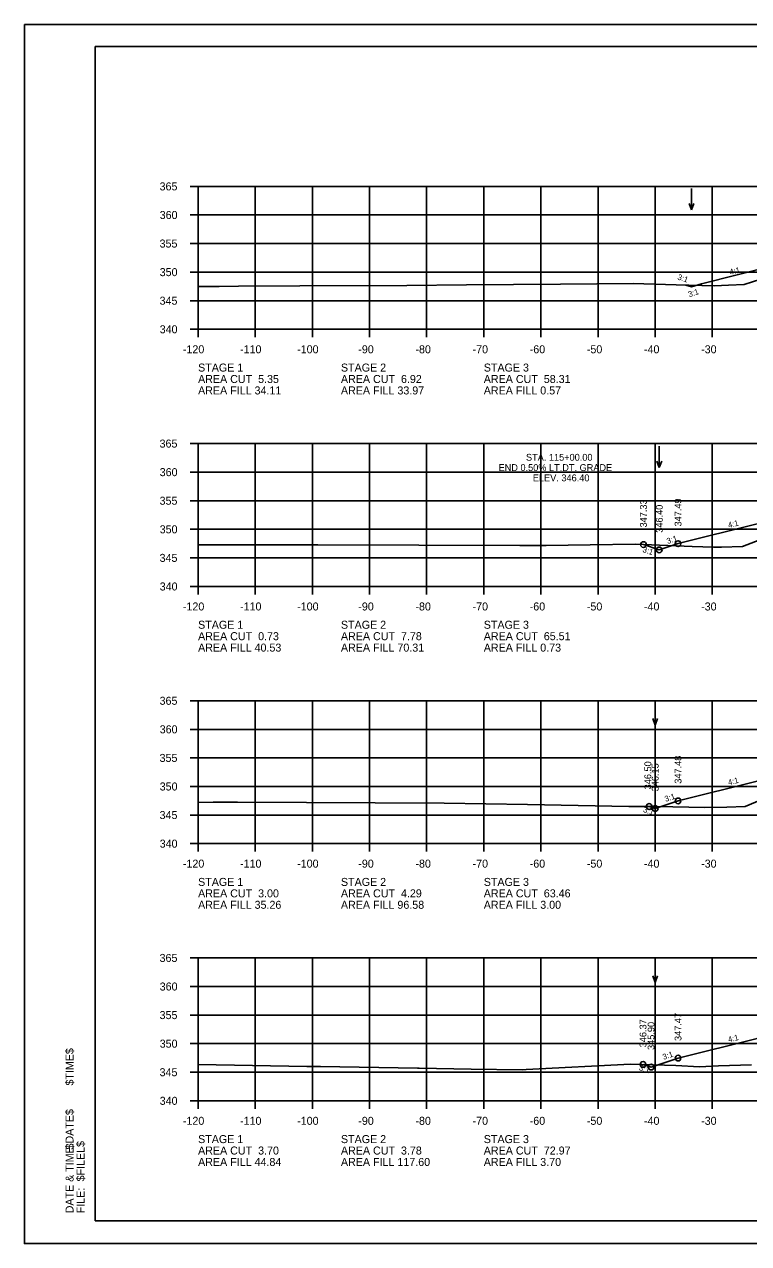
# Model space of a CAD drawing. Extents: x 1630712 to 1632516, y 782146 to 785403.
# Drawn here: x 1632182.6 to 1632309.3, y 784976.7 to 785190 of the extents above; entities that cross this region are included whole.
import ezdxf

# ---------------------------------------------------------------- set-up
doc = ezdxf.new("R2010")
doc.units = 0
for name, color, linetype in [('Default', 7, 'Continuous'), ('Notes', 7, 'Continuous'), ('R_Axis', 7, 'Continuous'), ('R_Axis Annot', 7, 'Continuous'), ('R_Border', 7, 'Continuous'), ('R_Exist Surface', 7, 'Continuous'), ('R_Fin Surface', 7, 'Continuous'), ('R_Grid', 7, 'Continuous'), ('R_No Plot', 7, 'Continuous'), ('R_Water Annot', 7, 'Continuous'), ('R_Xsect Elev', 7, 'Continuous'), ('R_Xsect Slope', 7, 'Continuous')]:
    doc.layers.add(name, color=color, linetype=linetype)

msp = doc.modelspace()

# ---------------------------------------------------------------- linework, layer by layer
at = {"layer": 'R_Axis'}
for p, q in [((1632211.56, 785161.65), (1632212.96, 785161.65)), ((1632212.96, 785136.65), (1632212.96, 785161.65)), ((1632211.56, 785156.65), (1632212.96, 785156.65)), ((1632211.56, 785151.65), (1632212.96, 785151.65)), ((1632211.56, 785146.65), (1632212.96, 785146.65)), ((1632211.56, 785141.65), (1632212.96, 785141.65)), ((1632211.56, 785136.65), (1632212.96, 785136.65)), ((1632212.96, 785136.65), (1632492.96, 785136.65)), ((1632212.96, 785135.25), (1632212.96, 785136.65)), ((1632222.96, 785135.25), (1632222.96, 785136.65)), ((1632232.96, 785135.25), (1632232.96, 785136.65)), ((1632242.96, 785135.25), (1632242.96, 785136.65)), ((1632252.96, 785135.25), (1632252.96, 785136.65)), ((1632262.96, 785135.25), (1632262.96, 785136.65)), ((1632272.96, 785135.25), (1632272.96, 785136.65)), ((1632282.96, 785135.25), (1632282.96, 785136.65)), ((1632292.96, 785135.25), (1632292.96, 785136.65)), ((1632302.96, 785135.25), (1632302.96, 785136.65)), ((1632211.56, 785116.65), (1632212.96, 785116.65)), ((1632212.96, 785091.65), (1632212.96, 785116.65)), ((1632211.56, 785111.65), (1632212.96, 785111.65)), ((1632211.56, 785106.65), (1632212.96, 785106.65)), ((1632211.56, 785101.65), (1632212.96, 785101.65)), ((1632211.56, 785096.65), (1632212.96, 785096.65)), ((1632211.56, 785091.65), (1632212.96, 785091.65)), ((1632212.96, 785091.65), (1632492.96, 785091.65)), ((1632212.96, 785090.25), (1632212.96, 785091.65)), ((1632222.96, 785090.25), (1632222.96, 785091.65)), ((1632232.96, 785090.25), (1632232.96, 785091.65)), ((1632242.96, 785090.25), (1632242.96, 785091.65)), ((1632252.96, 785090.25), (1632252.96, 785091.65)), ((1632262.96, 785090.25), (1632262.96, 785091.65)), ((1632272.96, 785090.25), (1632272.96, 785091.65)), ((1632282.96, 785090.25), (1632282.96, 785091.65)), ((1632292.96, 785090.25), (1632292.96, 785091.65)), ((1632302.96, 785090.25), (1632302.96, 785091.65)), ((1632211.56, 785071.65), (1632212.96, 785071.65)), ((1632212.96, 785046.65), (1632212.96, 785071.65)), ((1632211.56, 785066.65), (1632212.96, 785066.65)), ((1632211.56, 785061.65), (1632212.96, 785061.65)), ((1632211.56, 785056.65), (1632212.96, 785056.65)), ((1632211.56, 785051.65), (1632212.96, 785051.65)), ((1632211.56, 785046.65), (1632212.96, 785046.65)), ((1632212.96, 785046.65), (1632492.96, 785046.65)), ((1632212.96, 785045.25), (1632212.96, 785046.65)), ((1632222.96, 785045.25), (1632222.96, 785046.65)), ((1632232.96, 785045.25), (1632232.96, 785046.65)), ((1632242.96, 785045.25), (1632242.96, 785046.65)), ((1632252.96, 785045.25), (1632252.96, 785046.65)), ((1632262.96, 785045.25), (1632262.96, 785046.65)), ((1632272.96, 785045.25), (1632272.96, 785046.65)), ((1632282.96, 785045.25), (1632282.96, 785046.65)), ((1632292.96, 785045.25), (1632292.96, 785046.65)), ((1632302.96, 785045.25), (1632302.96, 785046.65)), ((1632211.56, 785026.65), (1632212.96, 785026.65)), ((1632212.96, 785001.65), (1632212.96, 785026.65)), ((1632211.56, 785021.65), (1632212.96, 785021.65)), ((1632211.56, 785016.65), (1632212.96, 785016.65)), ((1632211.56, 785011.65), (1632212.96, 785011.65)), ((1632211.56, 785006.65), (1632212.96, 785006.65)), ((1632211.56, 785001.65), (1632212.96, 785001.65)), ((1632212.96, 785001.65), (1632492.96, 785001.65)), ((1632212.96, 785000.25), (1632212.96, 785001.65)), ((1632222.96, 785000.25), (1632222.96, 785001.65)), ((1632232.96, 785000.25), (1632232.96, 785001.65)), ((1632242.96, 785000.25), (1632242.96, 785001.65)), ((1632252.96, 785000.25), (1632252.96, 785001.65)), ((1632262.96, 785000.25), (1632262.96, 785001.65)), ((1632272.96, 785000.25), (1632272.96, 785001.65)), ((1632282.96, 785000.25), (1632282.96, 785001.65)), ((1632292.96, 785000.25), (1632292.96, 785001.65)), ((1632302.96, 785000.25), (1632302.96, 785001.65))]:
    msp.add_line(p, q, dxfattribs=at)
at = {"layer": 'R_Border'}
for p, q in [((1632194.96, 785186.11), (1632511.14, 785186.11)), ((1632194.96, 784980.65), (1632194.96, 785186.11)), ((1632511.14, 784980.65), (1632194.96, 784980.65))]:
    msp.add_line(p, q, dxfattribs=at)
at = {"layer": 'R_Exist Surface'}
for points in [[(1632212.96, 785144.13), (1632216.65, 785144.16), (1632220.05, 785144.17), (1632230.79, 785144.24), (1632249.48, 785144.34), (1632259.91, 785144.4), (1632276.37, 785144.53), (1632289.09, 785144.64), (1632296.61, 785144.43), (1632303.35, 785144.26), (1632305.79, 785144.36), (1632308.53, 785144.47), (1632314.35, 785146.35)], [(1632212.96, 785098.92), (1632214.26, 785098.92), (1632223.77, 785098.93), (1632233.9, 785098.95), (1632269.28, 785098.79), (1632273.9, 785098.81), (1632281.6, 785098.95), (1632289.44, 785099.03), (1632299.42, 785098.66), (1632303.17, 785098.51), (1632304.56, 785098.55), (1632308.22, 785098.67), (1632312.8, 785100.37)], [(1632212.96, 785053.87), (1632215.59, 785053.88), (1632219.88, 785053.88), (1632256.02, 785053.73), (1632270.59, 785053.48), (1632288.33, 785053.17), (1632293.26, 785053.14), (1632301.67, 785052.95), (1632305.52, 785053.05), (1632308.69, 785053.12), (1632318.86, 785057.38)], [(1632212.96, 785007.99), (1632232.01, 785007.67), (1632232.29, 785007.67), (1632232.55, 785007.67), (1632234.37, 785007.64), (1632251.38, 785007.37), (1632251.65, 785007.36), (1632260.77, 785007.21), (1632269.7, 785007.08), (1632270.38, 785007.12), (1632288.66, 785008.08), (1632296.6, 785007.85), (1632300.74, 785007.62), (1632304.03, 785007.76), (1632309.82, 785007.95)]]:
    msp.add_lwpolyline(points, dxfattribs=at)
at = {"layer": 'R_Fin Surface'}
for points in [[(1632298.32, 785144.39), (1632299.33, 785144.06), (1632301.04, 785144.63), (1632313.58, 785147.76), (1632317.93, 785148.85), (1632321.86, 785149.01), (1632332.96, 785149.23), (1632343.43, 785149.02), (1632347.68, 785148.85), (1632352.01, 785147.77), (1632363.36, 785144.93), (1632364.81, 785145.41)], [(1632290.9, 785098.97), (1632293.68, 785098.05), (1632296.96, 785099.14), (1632310.79, 785102.6), (1632314.96, 785103.64), (1632320.96, 785103.88), (1632332.96, 785104.12), (1632344.96, 785103.88), (1632350.96, 785103.64), (1632355.14, 785102.6), (1632368.96, 785099.14), (1632368.98, 785099.14), (1632370.89, 785099.77)], [(1632291.9, 785053.15), (1632292.96, 785052.8), (1632296.96, 785054.13), (1632310.79, 785057.59), (1632314.96, 785058.63), (1632320.96, 785058.87), (1632332.96, 785059.11), (1632344.96, 785058.87), (1632350.96, 785058.63), (1632355.14, 785057.59), (1632368.96, 785054.13), (1632371.27, 785053.36), (1632373.07, 785053.96)], [(1632290.83, 785008.01), (1632292.24, 785007.55), (1632296.96, 785009.12), (1632310.79, 785012.58), (1632314.96, 785013.62), (1632320.96, 785013.86), (1632332.96, 785014.1), (1632344.96, 785013.86), (1632350.96, 785013.62), (1632355.14, 785012.58), (1632368.96, 785009.12), (1632373.57, 785007.59), (1632375.41, 785008.2)]]:
    msp.add_lwpolyline(points, dxfattribs=at)
at = {"layer": 'R_Grid'}
for p, q in [((1632212.96, 785161.65), (1632492.96, 785161.65)), ((1632212.96, 785136.65), (1632212.96, 785161.65)), ((1632222.96, 785136.65), (1632222.96, 785161.65)), ((1632232.96, 785136.65), (1632232.96, 785161.65)), ((1632242.96, 785136.65), (1632242.96, 785161.65)), ((1632252.96, 785136.65), (1632252.96, 785161.65)), ((1632262.96, 785136.65), (1632262.96, 785161.65)), ((1632272.96, 785136.65), (1632272.96, 785161.65)), ((1632282.96, 785136.65), (1632282.96, 785161.65)), ((1632292.96, 785136.65), (1632292.96, 785161.65)), ((1632302.96, 785136.65), (1632302.96, 785161.65)), ((1632212.96, 785156.65), (1632492.96, 785156.65)), ((1632212.96, 785151.65), (1632492.96, 785151.65)), ((1632212.96, 785146.65), (1632492.96, 785146.65)), ((1632212.96, 785141.65), (1632492.96, 785141.65)), ((1632212.96, 785136.65), (1632492.96, 785136.65)), ((1632212.96, 785116.65), (1632492.96, 785116.65)), ((1632212.96, 785091.65), (1632212.96, 785116.65)), ((1632222.96, 785091.65), (1632222.96, 785116.65)), ((1632232.96, 785091.65), (1632232.96, 785116.65)), ((1632242.96, 785091.65), (1632242.96, 785116.65)), ((1632252.96, 785091.65), (1632252.96, 785116.65)), ((1632262.96, 785091.65), (1632262.96, 785116.65)), ((1632272.96, 785091.65), (1632272.96, 785116.65)), ((1632282.96, 785091.65), (1632282.96, 785116.65)), ((1632292.96, 785091.65), (1632292.96, 785116.65)), ((1632302.96, 785091.65), (1632302.96, 785116.65)), ((1632212.96, 785111.65), (1632492.96, 785111.65)), ((1632212.96, 785106.65), (1632492.96, 785106.65)), ((1632212.96, 785101.65), (1632492.96, 785101.65)), ((1632212.96, 785096.65), (1632492.96, 785096.65)), ((1632212.96, 785091.65), (1632492.96, 785091.65)), ((1632212.96, 785071.65), (1632492.96, 785071.65)), ((1632212.96, 785046.65), (1632212.96, 785071.65)), ((1632222.96, 785046.65), (1632222.96, 785071.65)), ((1632232.96, 785046.65), (1632232.96, 785071.65)), ((1632242.96, 785046.65), (1632242.96, 785071.65)), ((1632252.96, 785046.65), (1632252.96, 785071.65)), ((1632262.96, 785046.65), (1632262.96, 785071.65)), ((1632272.96, 785046.65), (1632272.96, 785071.65)), ((1632282.96, 785046.65), (1632282.96, 785071.65)), ((1632292.96, 785046.65), (1632292.96, 785071.65)), ((1632302.96, 785046.65), (1632302.96, 785071.65)), ((1632212.96, 785066.65), (1632492.96, 785066.65)), ((1632212.96, 785061.65), (1632492.96, 785061.65)), ((1632212.96, 785056.65), (1632492.96, 785056.65)), ((1632212.96, 785051.65), (1632492.96, 785051.65)), ((1632212.96, 785046.65), (1632492.96, 785046.65)), ((1632212.96, 785026.65), (1632492.96, 785026.65)), ((1632212.96, 785001.65), (1632212.96, 785026.65)), ((1632222.96, 785001.65), (1632222.96, 785026.65)), ((1632232.96, 785001.65), (1632232.96, 785026.65)), ((1632242.96, 785001.65), (1632242.96, 785026.65)), ((1632252.96, 785001.65), (1632252.96, 785026.65)), ((1632262.96, 785001.65), (1632262.96, 785026.65)), ((1632272.96, 785001.65), (1632272.96, 785026.65)), ((1632282.96, 785001.65), (1632282.96, 785026.65)), ((1632292.96, 785001.65), (1632292.96, 785026.65)), ((1632302.96, 785001.65), (1632302.96, 785026.65)), ((1632212.96, 785021.65), (1632492.96, 785021.65)), ((1632212.96, 785016.65), (1632492.96, 785016.65)), ((1632212.96, 785011.65), (1632492.96, 785011.65)), ((1632212.96, 785006.65), (1632492.96, 785006.65)), ((1632212.96, 785001.65), (1632492.96, 785001.65))]:
    msp.add_line(p, q, dxfattribs=at)
at = {"layer": 'R_No Plot'}
for p, q in [((1632182.56, 785190), (1632515.9, 785190)), ((1632182.56, 784976.67), (1632515.9, 784976.67))]:
    msp.add_line(p, q, dxfattribs=at)
msp.add_lwpolyline([(1632182.56, 785190), (1632515.9, 785190), (1632515.9, 784976.66), (1632182.56, 784976.66)], close=True, dxfattribs=at)
for centre in [(1632290.9, 785098.97), (1632296.96, 785099.14), (1632293.68, 785098.05), (1632291.9, 785053.15), (1632292.96, 785052.8), (1632296.96, 785054.13), (1632290.83, 785008.01), (1632292.24, 785007.55), (1632296.96, 785009.12)]:
    msp.add_circle(centre, 0.5, dxfattribs=at)
at = {"layer": 'R_Water Annot'}
for p, q in [((1632299.33, 785161.3), (1632299.33, 785157.53)), ((1632299.33, 785157.53), (1632298.91, 785158.68)), ((1632299.33, 785157.53), (1632299.75, 785158.68)), ((1632293.68, 785116.22), (1632293.68, 785112.45)), ((1632293.68, 785112.45), (1632293.26, 785113.6)), ((1632293.68, 785112.45), (1632294.1, 785113.6)), ((1632292.96, 785071.17), (1632292.96, 785067.4)), ((1632292.96, 785067.4), (1632292.54, 785068.56)), ((1632292.96, 785067.4), (1632293.38, 785068.56)), ((1632292.96, 785026.14), (1632292.96, 785022.37)), ((1632292.96, 785022.37), (1632292.54, 785023.53)), ((1632292.96, 785022.37), (1632293.38, 785023.53))]:
    msp.add_line(p, q, dxfattribs=at)

# ---------------------------------------------------------------- texts
at = {"layer": 'Default'}
for s, height, p in [('$TIME$', 1.397, (1632191.16, 785004.32)), ('$DATE$', 1.397, (1632191.16, 784993.14)), ('DATE & TIME:', 1.3968, (1632191.16, 784981.97)), ('$FILEL$', 1.397, (1632193.08, 784987.55)), ('FILE: ', 1.397, (1632193.08, 784981.97))]:
    msp.add_text(s, height=height, rotation=90, dxfattribs=at).set_placement(p)
at = {"layer": 'Notes'}
for s, p in [('STA. 115+00.00', (1632270.35, 785113.65)), ('END 0.50% LT.DT. GRADE', (1632265.55, 785111.85)), ('ELEV. 346.40', (1632271.55, 785110.05))]:
    msp.add_text(s, height=1.2, dxfattribs=at).set_placement(p)
at = {"layer": 'R_Axis'}
for p in [(1632212.96, 785136.65), (1632212.96, 785091.65), (1632212.96, 785046.65), (1632212.96, 785001.65)]:
    msp.add_text('-', height=0.0001, dxfattribs=at).set_placement(p)
at = {"layer": 'R_Axis Annot'}
for s, p in [('365', (1632206.22, 785160.95)), ('360', (1632206.24, 785155.95)), ('355', (1632206.22, 785150.95)), ('350', (1632206.24, 785145.95)), ('345', (1632206.22, 785140.95)), ('340', (1632206.24, 785135.95)), ('-120', (1632210.3, 785132.45)), ('-110', (1632220.3, 785132.45)), ('-100', (1632230.3, 785132.45)), ('-90', (1632241, 785132.45)), ('-80', (1632251, 785132.45)), ('-70', (1632261, 785132.45)), ('-60', (1632271, 785132.45)), ('-50', (1632281, 785132.45)), ('-40', (1632291, 785132.45)), ('-30', (1632301, 785132.45)), ('STAGE 1', (1632212.96, 785129.25)), ('STAGE 2', (1632237.96, 785129.25)), ('STAGE 3', (1632262.96, 785129.25)), ('AREA CUT  5.35', (1632212.96, 785127.25)), ('AREA CUT  6.92', (1632237.96, 785127.25)), ('AREA CUT  58.31', (1632262.96, 785127.25)), ('AREA FILL 34.11', (1632212.96, 785125.25)), ('AREA FILL 33.97', (1632237.96, 785125.25)), ('AREA FILL 0.57', (1632262.96, 785125.25)), ('365', (1632206.22, 785115.95)), ('360', (1632206.24, 785110.95)), ('355', (1632206.22, 785105.95)), ('350', (1632206.24, 785100.95)), ('345', (1632206.22, 785095.95)), ('340', (1632206.24, 785090.95)), ('-120', (1632210.3, 785087.45)), ('-110', (1632220.3, 785087.45)), ('-100', (1632230.3, 785087.45)), ('-90', (1632241, 785087.45)), ('-80', (1632251, 785087.45)), ('-70', (1632261, 785087.45)), ('-60', (1632271, 785087.45)), ('-50', (1632281, 785087.45)), ('-40', (1632291, 785087.45)), ('-30', (1632301, 785087.45)), ('STAGE 1', (1632212.96, 785084.25)), ('STAGE 2', (1632237.96, 785084.25)), ('STAGE 3', (1632262.96, 785084.25)), ('AREA CUT  0.73', (1632212.96, 785082.25)), ('AREA CUT  7.78', (1632237.96, 785082.25)), ('AREA CUT  65.51', (1632262.96, 785082.25)), ('AREA FILL 40.53', (1632212.96, 785080.25)), ('AREA FILL 70.31', (1632237.96, 785080.25)), ('AREA FILL 0.73', (1632262.96, 785080.25)), ('365', (1632206.22, 785070.95)), ('360', (1632206.24, 785065.95)), ('355', (1632206.22, 785060.95)), ('350', (1632206.24, 785055.95)), ('345', (1632206.22, 785050.95)), ('340', (1632206.24, 785045.95)), ('-120', (1632210.3, 785042.45)), ('-110', (1632220.3, 785042.45)), ('-100', (1632230.3, 785042.45)), ('-90', (1632241, 785042.45)), ('-80', (1632251, 785042.45)), ('-70', (1632261, 785042.45)), ('-60', (1632271, 785042.45)), ('-50', (1632281, 785042.45)), ('-40', (1632291, 785042.45)), ('-30', (1632301, 785042.45)), ('STAGE 1', (1632212.96, 785039.25)), ('STAGE 2', (1632237.96, 785039.25)), ('STAGE 3', (1632262.96, 785039.25)), ('AREA CUT  3.00', (1632212.96, 785037.25)), ('AREA CUT  4.29', (1632237.96, 785037.25)), ('AREA CUT  63.46', (1632262.96, 785037.25)), ('AREA FILL 35.26', (1632212.96, 785035.25)), ('AREA FILL 96.58', (1632237.96, 785035.25)), ('AREA FILL 3.00', (1632262.96, 785035.25)), ('365', (1632206.22, 785025.95)), ('360', (1632206.24, 785020.95)), ('355', (1632206.22, 785015.95)), ('350', (1632206.24, 785010.95)), ('345', (1632206.22, 785005.95)), ('340', (1632206.24, 785000.95)), ('-120', (1632210.3, 784997.45)), ('-110', (1632220.3, 784997.45)), ('-100', (1632230.3, 784997.45)), ('-90', (1632241, 784997.45)), ('-80', (1632251, 784997.45)), ('-70', (1632261, 784997.45)), ('-60', (1632271, 784997.45)), ('-50', (1632281, 784997.45)), ('-40', (1632291, 784997.45)), ('-30', (1632301, 784997.45)), ('STAGE 1', (1632212.96, 784994.25)), ('STAGE 2', (1632237.96, 784994.25)), ('STAGE 3', (1632262.96, 784994.25)), ('AREA CUT  3.70', (1632212.96, 784992.25)), ('AREA CUT  3.78', (1632237.96, 784992.25)), ('AREA CUT  72.97', (1632262.96, 784992.25)), ('AREA FILL 44.84', (1632212.96, 784990.25)), ('AREA FILL 117.60', (1632237.96, 784990.25)), ('AREA FILL 3.70', (1632262.96, 784990.25))]:
    msp.add_text(s, height=1.4, dxfattribs=at).set_placement(p)
at = {"layer": 'R_Xsect Elev'}
for s, p in [('347.33', (1632291.5, 785101.97)), ('346.40', (1632294.28, 785101.05)), ('347.49', (1632297.56, 785102.14)), ('347.48', (1632297.56, 785057.13)), ('346.50', (1632292.27, 785056.15)), ('346.15', (1632293.56, 785055.8)), ('347.47', (1632297.56, 785012.12)), ('346.37', (1632291.43, 785011.01)), ('345.90', (1632292.84, 785010.55))]:
    msp.add_text(s, height=1.2, rotation=90, dxfattribs=at).set_placement(p)
at = {"layer": 'R_Xsect Slope'}
for s, rotation, p in [('4:1', 14.0362, (1632306.1, 785146.15)), ('3:1', 341.5651, (1632296.78, 785145.39)), ('3:1', 18.4349, (1632298.93, 785142.25)), ('4:1', 14.0362, (1632305.84, 785101.87)), ('3:1', 18.4349, (1632295.17, 785099.07)), ('3:1', 341.5651, (1632290.67, 785097.7)), ('4:1', 14.0362, (1632305.84, 785056.86)), ('3:1', 18.4349, (1632294.8, 785053.94)), ('3:1', 341.5651, (1632290.77, 785052.21)), ('4:1', 14.0362, (1632305.84, 785011.86)), ('3:1', 18.4349, (1632294.44, 785008.81)), ('3:1', 341.5651, (1632290.05, 785007.04))]:
    msp.add_text(s, height=1, rotation=rotation, dxfattribs=at).set_placement(p)

doc.saveas('drawing.dxf')
